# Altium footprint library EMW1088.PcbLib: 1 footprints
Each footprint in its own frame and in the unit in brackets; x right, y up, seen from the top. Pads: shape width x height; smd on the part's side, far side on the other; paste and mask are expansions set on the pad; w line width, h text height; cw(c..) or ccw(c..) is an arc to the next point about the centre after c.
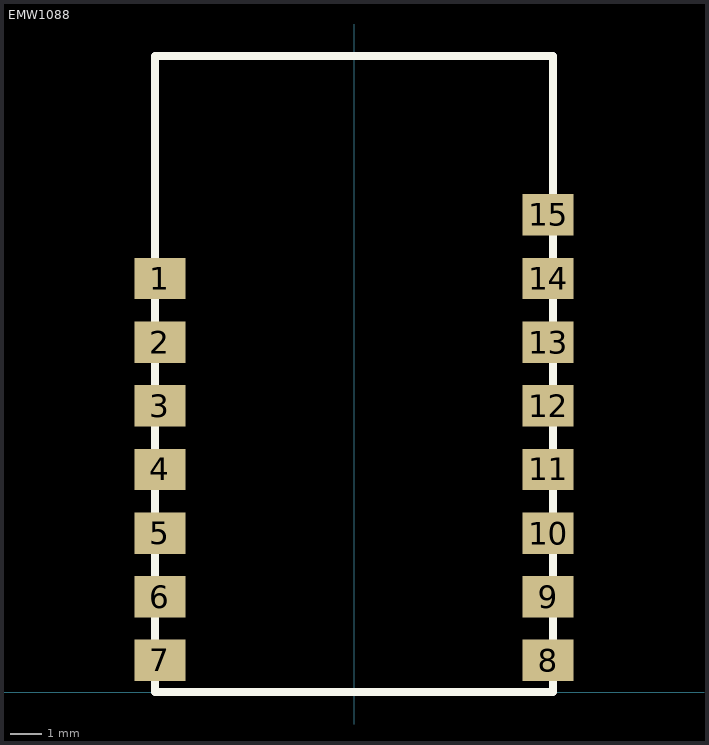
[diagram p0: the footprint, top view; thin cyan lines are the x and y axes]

## EMW1088 [mm]
pads (15):
  rect 1.6x1.3 smd: 1(-6.1,13) 2(-6.1,11) 3(-6.1,9) 4(-6.1,7) 5(-6.1,5) 6(-6.1,3) 7(-6.1,1) 8(6.1,1) 9(6.1,3) 10(6.1,5) 11(6.1,7) 12(6.1,9) 13(6.1,11) 14(6.1,13) 15(6.1,15)
Top Overlay:
  lines w0.254: -6.25,0 6.25,0 6.25,20 -6.25,20 -6.25,0
3D body: height 2.45, standoff 1.19, extent 2.357,16.247 5.357,19.347
3D body: height 0.6, standoff 0, extent -6.25,0 6.25,20
3D body: height 0.6, standoff 0, extent -6.25,10.5 -5.759,11.5
3D body: height 0.6, standoff 0, extent -6.25,6.55 -5.759,7.55
3D body: height 0.6, standoff 0, extent -6.25,8.55 -5.759,9.55
3D body: height 0.6, standoff 0, extent -6.25,12.55 -5.759,13.55
3D body: height 0.6, standoff 0, extent -6.25,4.55 -5.759,5.55
3D body: height 0.6, standoff 0, extent -6.25,2.55 -5.759,3.55
3D body: height 0.6, standoff 0, extent -6.25,0.55 -5.759,1.55
3D body: height 0.6, standoff 0, extent 5.759,0.45 6.25,1.45
3D body: height 0.6, standoff 0, extent 5.759,2.45 6.25,3.45
3D body: height 0.6, standoff 0, extent 5.759,4.45 6.25,5.45
3D body: height 0.6, standoff 0, extent 5.759,6.45 6.25,7.45
3D body: height 0.6, standoff 0, extent 5.759,8.45 6.25,9.45
3D body: height 0.6, standoff 0, extent 5.759,10.45 6.25,11.45
3D body: height 0.6, standoff 0, extent 5.759,12.45 6.25,13.45
3D body: height 0.6, standoff 0, extent 5.759,14.45 6.25,15.45
3D body: height 2.6, standoff 0.6, extent -5.2,0.05 5.2,15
